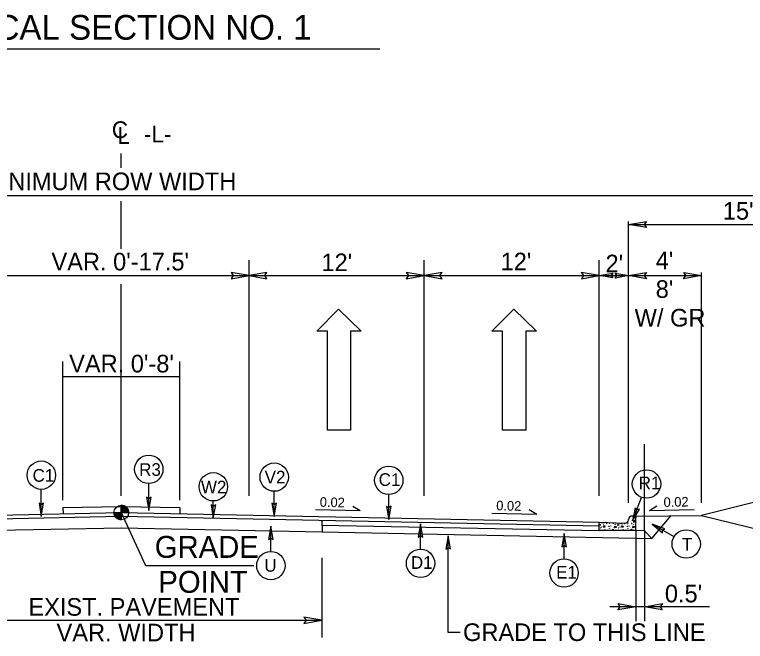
# Model space of a CAD drawing. Extents: x 3025871 to 3026431, y 707165 to 707825.
# Drawn here: x 3026166.8 to 3026216.8, y 707640.9 to 707683.9 of the extents above; entities that cross this region are included whole.
import ezdxf

# ---------------------------------------------------------------- set-up
doc = ezdxf.new("R2010")
doc.units = 0
for name, color, linetype in [('Prop Drainage Structure Junction Box with Manhole CELL', 7, 'Continuous'), ('Prop Drainage Structure Junction Box with Manhole Label', 7, 'Continuous'), ('Prop Drainage Structure Junction Box with Slab Lid CELL', 7, 'Continuous'), ('Prop Drainage Structure Junction Box with Slab Lid TB 840 34 CELL', 7, 'Continuous'), ('Prop Drainage Structure Plot Symbol 20 Scale', 7, 'Continuous'), ('Prop Drainage Structure Plot Symbol 50 Scale', 7, 'Continuous'), ('Prop Pavement Schedule Description CELL', 7, 'Continuous'), ('Sheet Data Field CELL', 7, 'Continuous'), ('Sheet Plot Border Inside CELL', 7, 'Continuous'), ('Sheet Sticker Incomplete CELL', 7, 'Continuous'), ('Sheet Typical CELL', 7, 'Continuous'), ('Typical Arrow Superelevation CELL', 7, 'Continuous'), ('Typical Curb CELL', 7, 'Continuous'), ('Typical Grade Point Symbol CELL', 7, 'Continuous'), ('Typical Shoulder Slope CELL', 7, 'Continuous'), ('Typical Text Centerline CELL', 7, 'Continuous'), ('Typical Text Grade Point CELL', 7, 'Continuous')]:
    doc.layers.add(name, color=color, linetype=linetype)

msp = doc.modelspace()

# ---------------------------------------------------------------- linework, layer by layer
at = {"layer": 'Prop Drainage Structure Junction Box with Manhole CELL'}
msp.add_line((3026187.813, 707648.426), (3026210.422, 707647.974), dxfattribs=at)
at = {"layer": 'Prop Drainage Structure Junction Box with Manhole Label'}
for p, q in [((3026174.061, 707673.352), (3026174.061, 707674.352)), ((3026174.061, 707667.815), (3026174.061, 707671.084)), ((3026174.061, 707650.898), (3026174.061, 707665.393))]:
    msp.add_line(p, q, dxfattribs=at)
at = {"layer": 'Prop Drainage Structure Junction Box with Slab Lid CELL'}
for p, q in [((3026174.061, 707649.743), (3026174.061, 707650.246)), ((3026173.558, 707649.743), (3026174.061, 707649.743)), ((3026174.06, 707649.239), (3026174.061, 707649.743)), ((3026174.061, 707649.743), (3026174.06, 707649.239)), ((3026174.565, 707649.743), (3026174.061, 707649.743))]:
    msp.add_line(p, q, dxfattribs=at)
for points in [[(3026174.066, 707650.246), (3026174.066, 707650.246), (3026174.066, 707649.743)], [(3026174.076, 707650.246), (3026174.076, 707649.743)], [(3026174.086, 707650.245), (3026174.086, 707649.743)], [(3026174.096, 707650.245), (3026174.096, 707649.743)], [(3026174.106, 707650.244), (3026174.106, 707649.743)], [(3026174.116, 707650.243), (3026174.116, 707649.743)], [(3026174.126, 707650.242), (3026174.126, 707649.743)], [(3026174.136, 707650.241), (3026174.136, 707649.743)], [(3026174.146, 707650.24), (3026174.146, 707649.743)], [(3026174.157, 707650.237), (3026174.156, 707649.743)], [(3026174.167, 707650.235), (3026174.166, 707649.743)], [(3026174.177, 707650.233), (3026174.177, 707649.743)], [(3026174.187, 707650.231), (3026174.187, 707649.743)], [(3026174.197, 707650.227), (3026174.197, 707649.743)], [(3026174.207, 707650.225), (3026174.207, 707649.743)], [(3026174.217, 707650.222), (3026174.217, 707649.743)], [(3026174.227, 707650.218), (3026174.227, 707649.743)], [(3026174.237, 707650.215), (3026174.237, 707649.743)], [(3026174.247, 707650.21), (3026174.247, 707649.743)], [(3026174.257, 707650.206), (3026174.257, 707649.743)], [(3026174.267, 707650.201), (3026174.267, 707649.743)], [(3026174.277, 707650.197), (3026174.277, 707649.743)], [(3026174.287, 707650.193), (3026174.287, 707649.743)], [(3026174.298, 707650.187), (3026174.297, 707649.743)], [(3026174.308, 707650.181), (3026174.307, 707649.743)], [(3026174.318, 707650.176), (3026174.318, 707649.743)], [(3026174.328, 707650.17), (3026174.328, 707649.743)], [(3026174.338, 707650.163), (3026174.338, 707649.743)], [(3026174.348, 707650.157), (3026174.348, 707649.743)], [(3026174.358, 707650.149), (3026174.358, 707649.743)], [(3026174.368, 707650.142), (3026174.368, 707649.743)], [(3026174.378, 707650.134), (3026174.378, 707649.743)], [(3026173.56, 707649.743), (3026173.56, 707649.688)], [(3026173.57, 707649.743), (3026173.57, 707649.629)], [(3026173.58, 707649.743), (3026173.58, 707649.593)], [(3026173.59, 707649.743), (3026173.59, 707649.563)], [(3026173.6, 707649.743), (3026173.6, 707649.539)], [(3026173.61, 707649.743), (3026173.61, 707649.518)], [(3026173.62, 707649.743), (3026173.62, 707649.499)], [(3026173.63, 707649.743), (3026173.63, 707649.481)], [(3026173.641, 707649.743), (3026173.64, 707649.465)], [(3026173.651, 707649.743), (3026173.651, 707649.451)], [(3026173.661, 707649.743), (3026173.661, 707649.437)], [(3026173.671, 707649.743), (3026173.671, 707649.425)], [(3026173.681, 707649.743), (3026173.681, 707649.413)], [(3026173.691, 707649.743), (3026173.691, 707649.402)], [(3026173.701, 707649.743), (3026173.701, 707649.39)], [(3026173.711, 707649.743), (3026173.711, 707649.38)], [(3026173.721, 707649.743), (3026173.721, 707649.371)], [(3026173.731, 707649.743), (3026173.731, 707649.362)], [(3026173.741, 707649.743), (3026173.741, 707649.353)], [(3026173.751, 707649.743), (3026173.751, 707649.346)], [(3026173.761, 707649.743), (3026173.761, 707649.338)], [(3026173.771, 707649.743), (3026173.771, 707649.331)], [(3026173.782, 707649.743), (3026173.781, 707649.324)], [(3026173.792, 707649.743), (3026173.791, 707649.318)], [(3026173.802, 707649.743), (3026173.802, 707649.311)], [(3026173.812, 707649.743), (3026173.812, 707649.305)], [(3026173.822, 707649.743), (3026173.822, 707649.3)], [(3026173.832, 707649.743), (3026173.832, 707649.294)], [(3026173.842, 707649.743), (3026173.842, 707649.29)], [(3026173.852, 707649.743), (3026173.852, 707649.285)], [(3026173.862, 707649.743), (3026173.862, 707649.281)], [(3026173.872, 707649.743), (3026173.872, 707649.276)], [(3026173.882, 707649.743), (3026173.882, 707649.272)], [(3026173.892, 707649.743), (3026173.892, 707649.268)], [(3026173.902, 707649.743), (3026173.902, 707649.265)], [(3026173.912, 707649.743), (3026173.912, 707649.262)], [(3026173.923, 707649.743), (3026173.922, 707649.259)], [(3026173.933, 707649.743), (3026173.932, 707649.256)], [(3026173.943, 707649.743), (3026173.943, 707649.254)], [(3026173.953, 707649.743), (3026173.953, 707649.252)], [(3026173.963, 707649.743), (3026173.963, 707649.249)], [(3026173.973, 707649.743), (3026173.973, 707649.247)], [(3026173.983, 707649.743), (3026173.983, 707649.246)], [(3026173.993, 707649.743), (3026173.993, 707649.244)], [(3026174.003, 707649.743), (3026174.003, 707649.243)], [(3026174.013, 707649.743), (3026174.013, 707649.242)], [(3026174.023, 707649.743), (3026174.023, 707649.24)], [(3026174.033, 707649.743), (3026174.033, 707649.24)], [(3026174.043, 707649.743), (3026174.043, 707649.239)], [(3026174.053, 707649.743), (3026174.053, 707649.239), (3026174.053, 707649.239)], [(3026174.388, 707650.125), (3026174.388, 707649.743)], [(3026174.398, 707650.116), (3026174.398, 707649.743)], [(3026174.408, 707650.107), (3026174.408, 707649.743)], [(3026174.418, 707650.097), (3026174.418, 707649.743)], [(3026174.428, 707650.087), (3026174.428, 707649.743)], [(3026174.438, 707650.076), (3026174.438, 707649.743)], [(3026174.449, 707650.064), (3026174.448, 707649.743)], [(3026174.459, 707650.051), (3026174.459, 707649.743)], [(3026174.469, 707650.038), (3026174.469, 707649.743)], [(3026174.479, 707650.023), (3026174.479, 707649.743)], [(3026174.489, 707650.008), (3026174.489, 707649.743)], [(3026174.499, 707649.991), (3026174.499, 707649.743)], [(3026174.509, 707649.973), (3026174.509, 707649.743)], [(3026174.519, 707649.952), (3026174.519, 707649.743)], [(3026174.529, 707649.928), (3026174.529, 707649.743)], [(3026174.539, 707649.9), (3026174.539, 707649.743)], [(3026174.549, 707649.866), (3026174.549, 707649.743)], [(3026174.559, 707649.814), (3026174.559, 707649.743)]]:
    msp.add_lwpolyline(points, dxfattribs=at)
msp.add_circle((3026174.061, 707649.743), 0.504, dxfattribs=at)
for start, end in [(359.9709, 89.9709), (179.9709, 269.9709)]:
    msp.add_arc((3026174.061, 707649.743), 0.504, start, end, dxfattribs=at)
at = {"layer": 'Prop Drainage Structure Junction Box with Slab Lid TB 840 34 CELL'}
for p, q in [((3026156.341, 707681.503), (3026191.781, 707681.503)), ((3026129.305, 707671.473), (3026223.819, 707671.473)), ((3026208.819, 707650.399), (3026208.819, 707669.684)), ((3026208.819, 707669.473), (3026223.819, 707669.473)), ((3026182.811, 707650.898), (3026182.811, 707667.04)), ((3026194.811, 707650.898), (3026194.811, 707667.04)), ((3026206.811, 707650.898), (3026206.811, 707667.04)), ((3026213.819, 707650.399), (3026213.819, 707666.184)), ((3026174.061, 707665.967), (3026153.311, 707665.967)), ((3026174.061, 707665.973), (3026206.811, 707665.973)), ((3026206.811, 707665.973), (3026213.819, 707665.973)), ((3026170.061, 707650.592), (3026170.061, 707660.092)), ((3026178.061, 707650.592), (3026178.061, 707660.092)), ((3026170.061, 707659.069), (3026178.061, 707659.069)), ((3026209.32, 707648.502), (3026209.32, 707642.305)), ((3026209.905, 707648.514), (3026209.905, 707642.305)), ((3026187.799, 707646.63), (3026187.799, 707641.192)), ((3026214.353, 707643.295), (3026207.533, 707643.294)), ((3026160.043, 707642.363), (3026187.799, 707642.363)), ((3026197.273, 707641.531), (3026196.463, 707641.531))]:
    msp.add_line(p, q, dxfattribs=at)
at = {"layer": 'Prop Drainage Structure Plot Symbol 20 Scale'}
msp.add_line((3026174.061, 707649.743), (3026175.724, 707646.115), dxfattribs=at)
at = {"layer": 'Prop Drainage Structure Plot Symbol 50 Scale'}
for p, q in [((3026208.818, 707649.255), (3026208.818, 707649.265)), ((3026209.32, 707649.506), (3026209.059, 707649.506)), ((3026209.129, 707649.171), (3026209.145, 707649.08)), ((3026209.283, 707649.126), (3026209.129, 707649.171)), ((3026209.32, 707648.502), (3026209.32, 707649.506)), ((3026206.811, 707648.502), (3026206.811, 707649.088)), ((3026206.811, 707649.088), (3026208.568, 707649.015)), ((3026207.073, 707648.743), (3026207.159, 707648.863)), ((3026207.194, 707648.749), (3026207.073, 707648.743)), ((3026207.159, 707648.863), (3026207.194, 707648.749)), ((3026207.841, 707648.692), (3026207.904, 707648.807)), ((3026208.007, 707648.731), (3026207.841, 707648.692)), ((3026207.904, 707648.807), (3026208.007, 707648.731)), ((3026208.327, 707648.743), (3026208.413, 707648.863)), ((3026208.447, 707648.749), (3026208.327, 707648.743)), ((3026208.413, 707648.863), (3026208.447, 707648.749)), ((3026209.094, 707648.692), (3026209.157, 707648.807)), ((3026209.26, 707648.731), (3026209.094, 707648.692)), ((3026209.145, 707649.08), (3026209.283, 707649.126)), ((3026209.157, 707648.807), (3026209.26, 707648.731)), ((3026209.32, 707648.502), (3026206.811, 707648.502))]:
    msp.add_line(p, q, dxfattribs=at)
for centre in [(3026209.089, 707649.43), (3026209.255, 707649.212), (3026209.307, 707649.395), (3026206.828, 707648.841), (3026206.845, 707648.938), (3026206.885, 707648.697), (3026206.901, 707648.904), (3026206.982, 707648.743), (3026207.01, 707649.029), (3026207.107, 707648.944), (3026207.153, 707649.046), (3026207.302, 707648.983), (3026207.331, 707648.881), (3026207.48, 707648.795), (3026207.509, 707648.967), (3026207.514, 707648.64), (3026207.526, 707649.017), (3026207.606, 707648.823), (3026207.783, 707648.989), (3026207.904, 707648.938), (3026208.082, 707648.841), (3026208.099, 707648.938), (3026208.139, 707648.697), (3026208.155, 707648.904), (3026208.235, 707648.743), (3026208.264, 707648.987), (3026208.361, 707648.944), (3026208.556, 707648.983), (3026208.585, 707648.881), (3026208.734, 707648.795), (3026208.762, 707648.967), (3026208.768, 707648.64), (3026208.779, 707649.017), (3026208.86, 707648.823), (3026209.037, 707648.989), (3026209.158, 707648.938), (3026206.822, 707648.531), (3026207.033, 707648.508), (3026207.193, 707648.577), (3026207.4, 707648.554), (3026207.572, 707648.526), (3026207.749, 707648.589), (3026207.921, 707648.548), (3026208.076, 707648.531), (3026208.287, 707648.508), (3026208.447, 707648.577), (3026208.653, 707648.554), (3026208.825, 707648.526), (3026209.003, 707648.589), (3026209.175, 707648.548)]:
    msp.add_circle(centre, 0.00805, dxfattribs=at)
for centre, start, end in [((3026208.578, 707649.255), 267.6155, 0), ((3026209.059, 707649.265), 90, 180)]:
    msp.add_arc(centre, 0.24, start, end, dxfattribs=at)
at = {"layer": 'Prop Pavement Schedule Description CELL'}
for p, q in [((3026170.062, 707650.079), (3026174.061, 707650.159)), ((3026174.061, 707650.159), (3026178.061, 707650.079)), ((3026141.311, 707649.088), (3026174.061, 707649.743)), ((3026170.062, 707650.079), (3026170.069, 707649.663)), ((3026174.061, 707649.743), (3026206.811, 707649.088)), ((3026178.061, 707650.079), (3026178.061, 707649.663)), ((3026141.311, 707648.838), (3026174.061, 707649.493)), ((3026174.061, 707649.493), (3026206.811, 707648.838)), ((3026187.809, 707649.218), (3026187.813, 707648.426)), ((3026160.043, 707648.421), (3026174.081, 707648.701)), ((3026174.041, 707648.701), (3026187.813, 707648.426)), ((3026187.81, 707648.884), (3026206.811, 707648.504))]:
    msp.add_line(p, q, dxfattribs=at)
at = {"layer": 'Sheet Data Field CELL'}
for p, q in [((3026187.454, 707662.162), (3026188.953, 707663.685)), ((3026188.953, 707663.685), (3026190.5, 707662.162)), ((3026199.454, 707662.162), (3026200.953, 707663.685)), ((3026200.953, 707663.685), (3026202.5, 707662.162)), ((3026188.179, 707662.162), (3026187.454, 707662.162)), ((3026188.179, 707655.392), (3026188.179, 707662.162)), ((3026190.5, 707662.162), (3026189.775, 707662.162)), ((3026189.775, 707662.162), (3026189.775, 707655.392)), ((3026200.179, 707662.162), (3026199.454, 707662.162)), ((3026200.179, 707655.392), (3026200.179, 707662.162)), ((3026202.5, 707662.162), (3026201.775, 707662.162)), ((3026201.775, 707662.162), (3026201.775, 707655.392)), ((3026189.775, 707655.392), (3026188.179, 707655.392)), ((3026201.775, 707655.392), (3026200.179, 707655.392))]:
    msp.add_line(p, q, dxfattribs=at)
at = {"layer": 'Sheet Plot Border Inside CELL'}
msp.add_line((3026209.905, 707648.49), (3026209.32, 707648.502), dxfattribs=at)
at = {"layer": 'Sheet Sticker Incomplete CELL'}
for p, q in [((3026190.432, 707649.853), (3026189.918, 707650.168)), ((3026210.241, 707649.889), (3026210.756, 707650.2)), ((3026190.432, 707649.853), (3026187.365, 707649.93)), ((3026202.522, 707649.612), (3026199.455, 707649.688)), ((3026202.522, 707649.612), (3026202.009, 707649.926)), ((3026210.241, 707649.889), (3026213.309, 707649.95))]:
    msp.add_line(p, q, dxfattribs=at)
at = {"layer": 'Sheet Typical CELL'}
for p, q in [((3026209.32, 707649.506), (3026213.819, 707649.55)), ((3026210.422, 707647.974), (3026211.745, 707649.53)), ((3026209.905, 707648.49), (3026210.422, 707647.974))]:
    msp.add_line(p, q, dxfattribs=at)
at = {"layer": 'Typical Curb CELL'}
msp.add_line((3026209.905, 707648.49), (3026209.905, 707654.429), dxfattribs=at)
at = {"layer": 'Typical Grade Point Symbol CELL'}
for p, q in [((3026175.946, 707649.88), (3026175.945, 707651.735)), ((3026168.579, 707649.476), (3026168.578, 707651.331)), ((3026184.54, 707649.472), (3026184.539, 707651.197)), ((3026192.389, 707649.258), (3026192.388, 707650.982)), ((3026209.097, 707649.171), (3026209.703, 707650.785)), ((3026180.366, 707649.367), (3026180.365, 707650.535)), ((3026184.308, 707647.082), (3026184.307, 707648.806)), ((3026194.565, 707647.24), (3026194.564, 707648.965)), ((3026211.931, 707648.082), (3026210.445, 707648.958)), ((3026196.463, 707641.531), (3026196.459, 707648.158)), ((3026204.4, 707646.576), (3026204.399, 707648.301))]:
    msp.add_line(p, q, dxfattribs=at)
for centre in [(3026175.945, 707652.707), (3026168.578, 707652.303), (3026184.539, 707652.169), (3026192.388, 707651.954), (3026210.046, 707651.695), (3026180.365, 707651.507), (3026212.768, 707647.587), (3026194.565, 707646.268), (3026184.308, 707646.11), (3026204.4, 707645.604)]:
    msp.add_circle(centre, 0.972, dxfattribs=at)
at = {"layer": 'Typical Shoulder Slope CELL'}
msp.add_line((3026175.724, 707646.115), (3026183.136, 707646.112), dxfattribs=at)
at = {"layer": 'Typical Text Centerline CELL'}
for points in [[(3026210.044, 707669.262), (3026208.819, 707669.473), (3026210.051, 707669.691), (3026209.895, 707669.473)], [(3026181.586, 707665.762), (3026182.811, 707665.973), (3026181.579, 707666.191), (3026181.736, 707665.973)], [(3026184.036, 707666.184), (3026182.811, 707665.973), (3026184.043, 707665.755), (3026183.887, 707665.973)], [(3026193.586, 707665.762), (3026194.811, 707665.973), (3026193.579, 707666.191), (3026193.736, 707665.973)], [(3026196.036, 707666.184), (3026194.811, 707665.973), (3026196.043, 707665.755), (3026195.887, 707665.973)], [(3026205.586, 707665.762), (3026206.811, 707665.973), (3026205.579, 707666.191), (3026205.736, 707665.973)], [(3026210.044, 707665.762), (3026208.819, 707665.973), (3026210.051, 707666.191), (3026209.895, 707665.973)], [(3026212.594, 707666.184), (3026213.819, 707665.973), (3026212.587, 707665.755), (3026212.744, 707665.973)], [(3026207.73, 707665.815), (3026206.811, 707665.973), (3026207.735, 707666.137), (3026207.618, 707665.973)], [(3026207.901, 707666.132), (3026208.82, 707665.973), (3026207.896, 707665.81), (3026208.013, 707665.973)], [(3026175.789, 707650.79), (3026175.946, 707649.88), (3026176.107, 707650.795), (3026175.945, 707650.679)], [(3026168.422, 707650.385), (3026168.579, 707649.476), (3026168.74, 707650.391), (3026168.579, 707650.274)], [(3026180.209, 707650.276), (3026180.366, 707649.367), (3026180.527, 707650.281), (3026180.365, 707650.165)], [(3026184.382, 707650.382), (3026184.54, 707649.472), (3026184.701, 707650.387), (3026184.539, 707650.271)], [(3026192.232, 707650.167), (3026192.389, 707649.258), (3026192.55, 707650.173), (3026192.388, 707650.056)], [(3026209.27, 707650.077), (3026209.097, 707649.171), (3026209.57, 707649.97), (3026209.378, 707649.918)], [(3026184.464, 707647.897), (3026184.307, 707648.806), (3026184.146, 707647.892), (3026184.308, 707648.008)], [(3026194.721, 707648.055), (3026194.564, 707648.965), (3026194.402, 707648.05), (3026194.564, 707648.166)], [(3026211.309, 707648.631), (3026210.445, 707648.958), (3026211.151, 707648.354), (3026211.133, 707648.552)], [(3026196.616, 707647.248), (3026196.459, 707648.158), (3026196.298, 707647.243), (3026196.46, 707647.36)], [(3026204.556, 707647.391), (3026204.399, 707648.301), (3026204.238, 707647.386), (3026204.4, 707647.502)], [(3026208.096, 707643.505), (3026209.321, 707643.294), (3026208.089, 707643.076), (3026208.245, 707643.294)], [(3026211.13, 707643.083), (3026209.905, 707643.294), (3026211.137, 707643.512), (3026210.98, 707643.294)], [(3026186.574, 707642.152), (3026187.799, 707642.363), (3026186.567, 707642.58), (3026186.724, 707642.363)]]:
    msp.add_lwpolyline(points, close=True, dxfattribs=at)
at = {"layer": 'Typical Text Grade Point CELL'}
for p, q in [((3026226.984, 707652.841), (3026213.819, 707649.55)), ((3026213.819, 707649.55), (3026226.984, 707646.259))]:
    msp.add_line(p, q, dxfattribs=at)

# ---------------------------------------------------------------- texts
at = {"layer": 'Prop Drainage Structure Junction Box with Manhole Label'}
msp.add_text('C', height=1.152, dxfattribs=at).set_placement((3026173.41, 707675.393))
for s, height, p in [('-L-', 1.1523, (3026175.611, 707675.102)), ('L', 1.152, (3026173.793, 707675))]:
    msp.add_text(s, height=height, rotation=359.9469, dxfattribs=at).set_placement(p)
at = {"layer": 'Prop Drainage Structure Junction Box with Slab Lid TB 840 34 CELL'}
msp.add_text('TYPICAL SECTION NO. 1 ', height=1.69489, rotation=360, dxfattribs=at).set_placement((3026160.406, 707682.136))
for s, height, p in [('MINIMUM ROW WIDTH', 1.20892, (3026164.522, 707671.829)), ("15'", 1.2089, (3026215.277, 707669.808)), ("VAR. 0'-17.5'", 1.20892, (3026169.277, 707666.329)), ("12'", 1.2089, (3026187.775, 707666.281)), ("12'", 1.2089, (3026200.05, 707666.335)), ("2'", 1.2089, (3026207.239, 707666.199)), ("4'", 1.2089, (3026210.677, 707666.415)), ("8'", 1.2089, (3026210.677, 707664.45)), ('W/ GR', 1.2089, (3026209.234, 707662.486)), ("VAR. 0'-8'", 1.2089, (3026170.489, 707659.343)), ("0.5'", 1.2089, (3026211.305, 707643.59)), ('EXIST. PAVEMENT', 1.20892, (3026167.694, 707642.674)), ('VAR. WIDTH', 1.2089, (3026169.625, 707640.917)), ('GRADE TO THIS LINE', 1.20892, (3026197.476, 707640.941))]:
    msp.add_text(s, height=height, dxfattribs=at).set_placement(p)
at = {"layer": 'Sheet Sticker Incomplete CELL'}
for s, rotation, p in [('0.02', 358.5679, (3026187.654, 707650.141)), ('0.02 ', 1.2029, (3026211.222, 707650.125)), ('0.02', 358.5679, (3026199.745, 707649.899))]:
    msp.add_text(s, height=0.6583, rotation=rotation, dxfattribs=at).set_placement(p)
at = {"layer": 'Typical Arrow Superelevation CELL'}
for s, p in [('R3', (3026175.285, 707652.255)), ('C1', (3026167.982, 707651.851)), ('V2', (3026183.884, 707651.734)), ('C1', (3026191.695, 707651.566)), ('W2', (3026179.518, 707651.055)), ('D1', (3026193.901, 707645.885)), ('U', (3026183.86, 707645.691)), ('E1', (3026203.855, 707645.221))]:
    msp.add_text(s, height=0.87, dxfattribs=at).set_placement(p)
for s, p in [('R1', (3026209.508, 707651.337)), ('T', (3026212.484, 707647.136))]:
    msp.add_text(s, height=0.87, rotation=360, dxfattribs=at).set_placement(p)
at = {"layer": 'Typical Shoulder Slope CELL'}
for s, p in [('GRADE', (3026176.353, 707646.641)), ('POINT', (3026176.598, 707644.245))]:
    msp.add_text(s, height=1.5, rotation=359.9804, dxfattribs=at).set_placement(p)

doc.saveas('drawing.dxf')
